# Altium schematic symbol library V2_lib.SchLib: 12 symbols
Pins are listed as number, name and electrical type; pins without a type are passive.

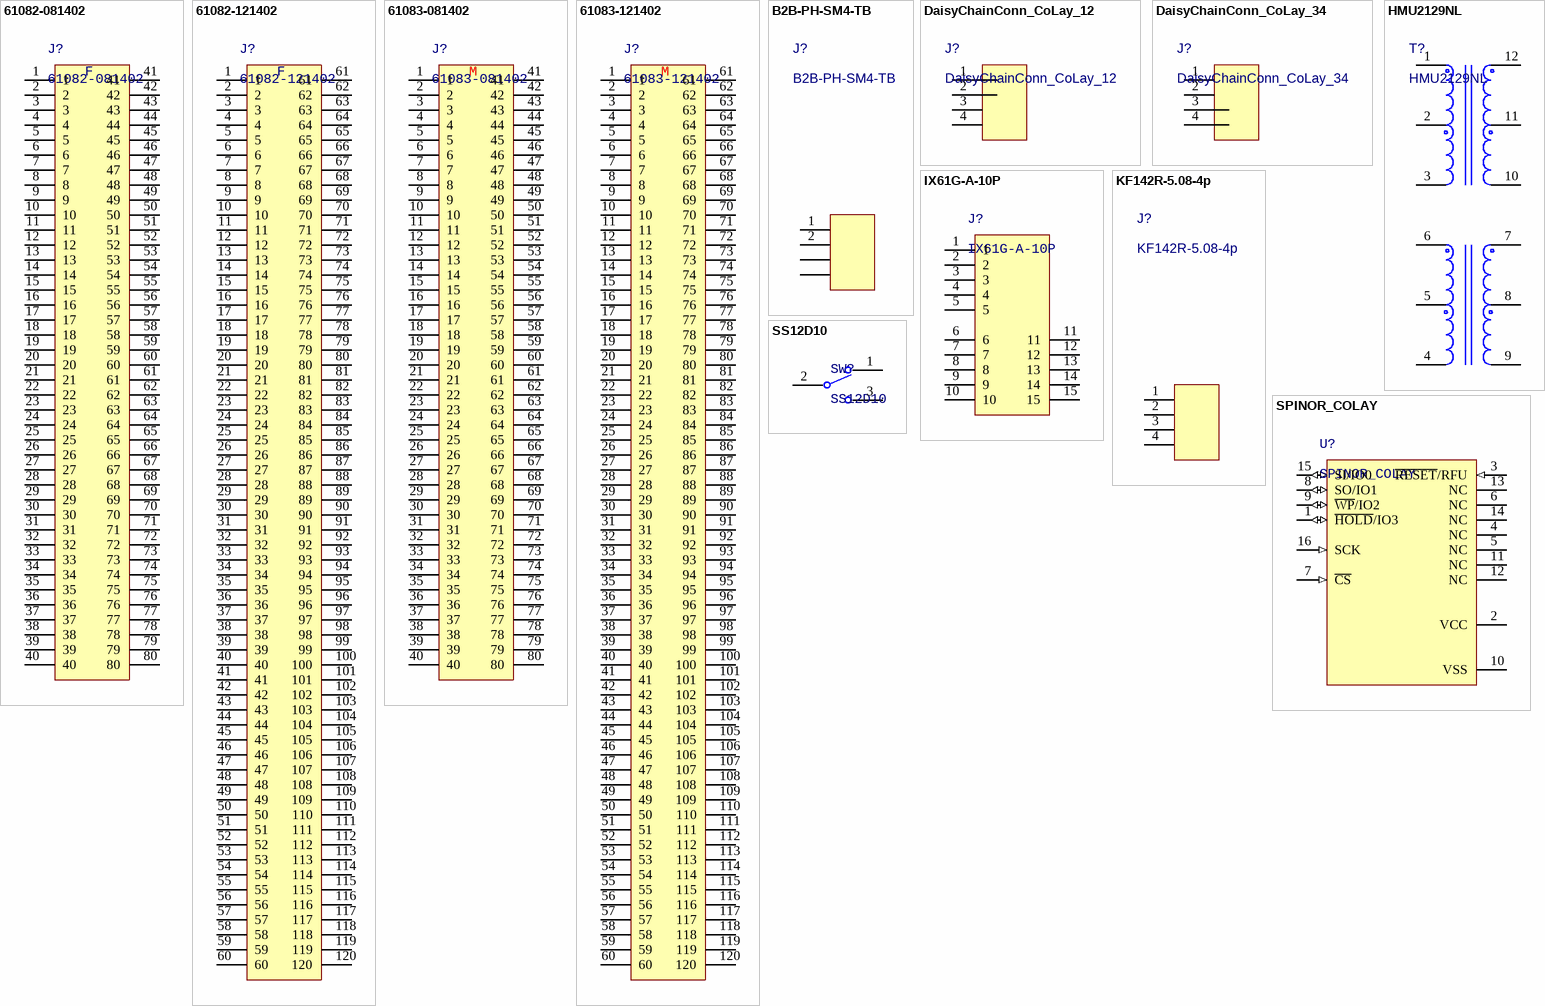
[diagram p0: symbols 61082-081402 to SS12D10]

## 61082-081402
designator J?
footprint 61082-081402 (Bergstak 0.8mm Board-to-Board Connector, Receptable, 80 Pos)
pins: 1, 2, 3, 4, 5, 6, 7, 8, 9, 10, 11, 12, 13, 14, 15, 16, 17, 18, 19, 20, 21, 22, 23, 24, 25, 26, 27, 28, 29, 30, 31, 32, 33, 34, 35, 36, 37, 38, 39, 40, 41, 42, 43, 44, 45, 46, 47, 48, 49, 50, 51, 52, 53, 54, 55, 56, 57, 58, 59, 60, 61, 62, 63, 64, 65, 66, 67, 68, 69, 70, 71, 72, 73, 74, 75, 76, 77, 78, 79, 80

## 61082-121402
designator J?
footprint 61082-121402 (Bergstak 0.8mm Board-to-Board Connector, Receptable, 120 Pos, 4.7mm)
pins: 1, 2, 3, 4, 5, 6, 7, 8, 9, 10, 11, 12, 13, 14, 15, 16, 17, 18, 19, 20, 21, 22, 23, 24, 25, 26, 27, 28, 29, 30, 31, 32, 33, 34, 35, 36, 37, 38, 39, 40, 41, 42, 43, 44, 45, 46, 47, 48, 49, 50, 51, 52, 53, 54, 55, 56, 57, 58, 59, 60, 61, 62, 63, 64, 65, 66, 67, 68, 69, 70, 71, 72, 73, 74, 75, 76, 77, 78, 79, 80, 81, 82, 83, 84, 85, 86, 87, 88, 89, 90, 91, 92, 93, 94, 95, 96, 97, 98, 99, 100, 101, 102, 103, 104, 105, 106, 107, 108, 109, 110, 111, 112, 113, 114, 115, 116, 117, 118, 119, 120

## 61083-081402
designator J?
footprint 61083-081402 (Bergstak 0.8mm Board-to-Board Connector, Plug, 80 Pos)
pins: 1, 2, 3, 4, 5, 6, 7, 8, 9, 10, 11, 12, 13, 14, 15, 16, 17, 18, 19, 20, 21, 22, 23, 24, 25, 26, 27, 28, 29, 30, 31, 32, 33, 34, 35, 36, 37, 38, 39, 40, 41, 42, 43, 44, 45, 46, 47, 48, 49, 50, 51, 52, 53, 54, 55, 56, 57, 58, 59, 60, 61, 62, 63, 64, 65, 66, 67, 68, 69, 70, 71, 72, 73, 74, 75, 76, 77, 78, 79, 80

## 61083-121402
designator J?
footprint 61083-121402 (Bergstak 0.8mm Board-to-Board Connector, Plug, 120 Pos, 3.7mm)
pins: 1, 2, 3, 4, 5, 6, 7, 8, 9, 10, 11, 12, 13, 14, 15, 16, 17, 18, 19, 20, 21, 22, 23, 24, 25, 26, 27, 28, 29, 30, 31, 32, 33, 34, 35, 36, 37, 38, 39, 40, 41, 42, 43, 44, 45, 46, 47, 48, 49, 50, 51, 52, 53, 54, 55, 56, 57, 58, 59, 60, 61, 62, 63, 64, 65, 66, 67, 68, 69, 70, 71, 72, 73, 74, 75, 76, 77, 78, 79, 80, 81, 82, 83, 84, 85, 86, 87, 88, 89, 90, 91, 92, 93, 94, 95, 96, 97, 98, 99, 100, 101, 102, 103, 104, 105, 106, 107, 108, 109, 110, 111, 112, 113, 114, 115, 116, 117, 118, 119, 120

## B2B-PH-SM4-TB
designator J?
footprint B2B-PH-SM4-TB
pins: 1, 2, 3, 4

## DaisyChainConn_CoLay_12
designator J?
footprint DaisyChainConn_CoLay_12 (Header(shrouded), 2.54mm, 4x1, R/A, TH)
pins: 1, 2, 3, 4

## DaisyChainConn_CoLay_34
designator J?
footprint DaisyChainConn_CoLay_34 (Header(shrouded), 2.54mm, 4x1, R/A, TH)
pins: 1, 2, 3, 4

## HMU2129NL
designator T?
BMS TRANSFORMER
footprint HMU2129NL (SOP, 12-Leads, Body 14.65x11.50mm, Pitch 2.00mm, IPC Low Density)
pins: 1 TD+, 2 TCT, 3 TD-, 4 TD+, 5 TCT, 6 TD-, 7 TX-, 8 CMT, 9 TX+, 10 TX-, 11 CMT, 12 TX+

## IX61G-A-10P
designator J?
footprint IX61G-A-10P
pins: 1, 2, 3, 4, 5, 6, 7, 8, 9, 10, 11, 12, 13, 14, 15

## KF142R-5.08-4p
designator J?
footprint KF142R-5.08-4p
pins: 1, 2, 3, 4

## SPINOR_COLAY
designator U?
footprint SPINOR_COLAY
pins: 1 ~{HOLD}/IO3 (io), 2 VCC (power), 3 ~{RESET}/RFU (in), 4 NC, 5 NC, 6 NC, 7 ~{CS} (in), 8 SO/IO1 (io), 9 ~{WP}/IO2 (io), 10 VSS (power), 11 NC, 12 NC, 13 NC, 14 NC (power), 15 SI/IO0 (io), 16 SCK (in)

## SS12D10
designator SW?
footprint SS12D10
pins: 1, 2 2(COM), 3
